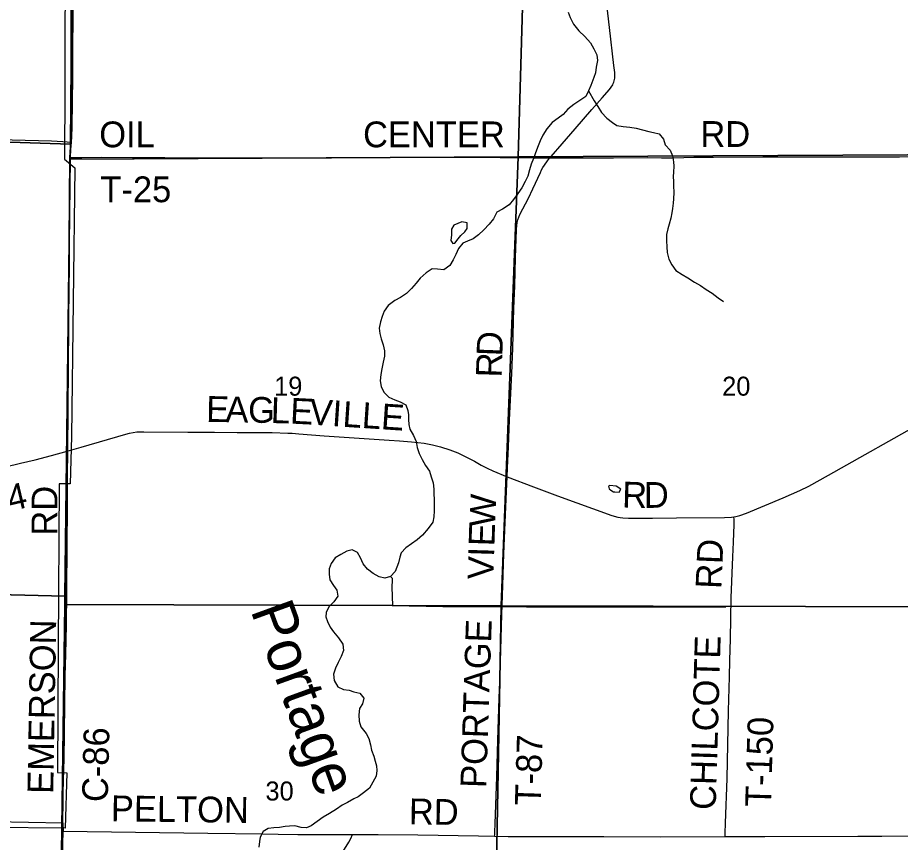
# Model space of a CAD drawing. Extents: x 1443599 to 1910620, y 1028088 to 1361369.
# Drawn here: x 1682963 to 1693235, y 1162784 to 1172379 of the extents above; entities that cross this region are included whole.
import ezdxf

# ---------------------------------------------------------------- set-up
doc = ezdxf.new("R2010")
doc.units = 0
for name, color, linetype in [('GM_X_County_Road', 7, 'Continuous'), ('GM_X_County_Road_Text', 7, 'Continuous'), ('GM_X_Major_River', 7, 'Continuous'), ('GM_X_Major_River_Text', 7, 'Continuous'), ('GM_X_Minor_Lake', 7, 'Continuous'), ('GM_X_Minor_River', 7, 'Continuous'), ('GM_X_Section', 7, 'Continuous'), ('GM_X_Section_Text', 7, 'Continuous'), ('GM_X_Township', 7, 'Continuous'), ('GM_X_Township_Road', 7, 'Continuous'), ('GM_X_Township_Road_Text', 7, 'Continuous')]:
    doc.layers.add(name, color=color, linetype=linetype)

msp = doc.modelspace()

# ---------------------------------------------------------------- linework, layer by layer
at = {"layer": 'GM_X_County_Road'}
for points in [[(1683590, 1170929), (1683595, 1170994), (1683598, 1171109), (1683605, 1171686), (1683607, 1172060), (1683609, 1172350), (1683612, 1172924), (1683614, 1173254), (1683611, 1173384)], [(1683579, 1170752), (1683583, 1170847), (1683590, 1170929)], [(1683539, 1167334), (1683542, 1167414), (1683546, 1167591), (1683550, 1167869), (1683552, 1168070), (1683556, 1168581), (1683559, 1168893), (1683563, 1169270), (1683565, 1169433), (1683567, 1169742), (1683570, 1170087), (1683572, 1170399), (1683575, 1170650), (1683579, 1170752)], [(1683490, 1163011), (1683489, 1163099), (1683491, 1163314), (1683495, 1163492), (1683502, 1163642), (1683506, 1163744), (1683509, 1164063), (1683513, 1164388), (1683518, 1164721), (1683523, 1164974), (1683531, 1165312), (1683537, 1165698), (1683539, 1166255), (1683542, 1166665), (1683543, 1166892), (1683538, 1167107), (1683537, 1167264), (1683539, 1167334)], [(1678210, 1163117), (1678747, 1163103), (1679108, 1163091), (1680009, 1163079), (1680419, 1163071), (1681435, 1163051), (1682288, 1163036), (1683490, 1163011)], [(1683490, 1163011), (1683492, 1162913)], [(1683492, 1162913), (1685175, 1162891), (1685815, 1162884), (1685995, 1162880), (1686225, 1162875), (1686619, 1162877), (1686861, 1162877)], [(1686861, 1162877), (1687160, 1162876), (1687620, 1162872), (1688326, 1162859), (1688514, 1162855)], [(1688514, 1162855), (1688670, 1162851), (1689786, 1162851), (1690443, 1162850), (1691195, 1162851)], [(1691195, 1162851), (1691657, 1162851), (1692741, 1162856), (1693020, 1162857), (1693834, 1162862)]]:
    msp.add_lwpolyline(points, dxfattribs=at)
at = {"layer": 'GM_X_Major_River'}
for points in [[(1689368, 1172444), (1689394, 1172379), (1689433, 1172305), (1689495, 1172225), (1689563, 1172158), (1689630, 1172086), (1689670, 1172018), (1689704, 1171947), (1689712, 1171879), (1689697, 1171805), (1689687, 1171737), (1689669, 1171682)], [(1689669, 1171682), (1689634, 1171591), (1689606, 1171529), (1689574, 1171462), (1689506, 1171416), (1689435, 1171367), (1689367, 1171315), (1689311, 1171253), (1689253, 1171211), (1689182, 1171159), (1689123, 1171085), (1689075, 1171012), (1689043, 1170945), (1689014, 1170870), (1688984, 1170795), (1688966, 1170741), (1688940, 1170674), (1688921, 1170608), (1688901, 1170535), (1688869, 1170472), (1688829, 1170399), (1688784, 1170334), (1688732, 1170264), (1688682, 1170203), (1688606, 1170152), (1688541, 1170116), (1688501, 1170039), (1688450, 1169975), (1688390, 1169909), (1688328, 1169851), (1688265, 1169805), (1688198, 1169777), (1688145, 1169757), (1688093, 1169694), (1688063, 1169623), (1688033, 1169562), (1687992, 1169495), (1687921, 1169447), (1687851, 1169454), (1687787, 1169456), (1687718, 1169412), (1687649, 1169350), (1687599, 1169290), (1687547, 1169228), (1687488, 1169171), (1687418, 1169122), (1687351, 1169088), (1687275, 1169032), (1687227, 1168966), (1687207, 1168902), (1687184, 1168839), (1687172, 1168767), (1687178, 1168703), (1687192, 1168642), (1687216, 1168573), (1687234, 1168504), (1687231, 1168440), (1687217, 1168369), (1687201, 1168295), (1687188, 1168229), (1687182, 1168155), (1687194, 1168089), (1687224, 1168020), (1687284, 1167964), (1687351, 1167933), (1687414, 1167909), (1687479, 1167875), (1687503, 1167808), (1687511, 1167757), (1687513, 1167703), (1687516, 1167647), (1687526, 1167591), (1687569, 1167519), (1687599, 1167448), (1687611, 1167379), (1687637, 1167308), (1687670, 1167239), (1687708, 1167168), (1687758, 1167102), (1687774, 1167037), (1687799, 1166968), (1687805, 1166892), (1687807, 1166839), (1687809, 1166773), (1687811, 1166713), (1687811, 1166641), (1687807, 1166573), (1687796, 1166511), (1687742, 1166437), (1687673, 1166359), (1687612, 1166303), (1687546, 1166259), (1687482, 1166211), (1687425, 1166153), (1687409, 1166101), (1687395, 1166038), (1687355, 1165935), (1687301, 1165877), (1687235, 1165859), (1687169, 1165873), (1687102, 1165911)], [(1687102, 1165911), (1687034, 1165962), (1686984, 1166026), (1686952, 1166093), (1686920, 1166156), (1686855, 1166186), (1686793, 1166172), (1686725, 1166134), (1686658, 1166095), (1686612, 1166030), (1686590, 1165965), (1686588, 1165903), (1686598, 1165838), (1686640, 1165773), (1686678, 1165717), (1686688, 1165649), (1686643, 1165584), (1686585, 1165524), (1686553, 1165459), (1686551, 1165407), (1686568, 1165354), (1686602, 1165287), (1686640, 1165235), (1686698, 1165163), (1686747, 1165088), (1686755, 1165017), (1686730, 1164946), (1686692, 1164877), (1686662, 1164810), (1686638, 1164741), (1686645, 1164668), (1686689, 1164593), (1686754, 1164564), (1686822, 1164554), (1686875, 1164536), (1686945, 1164518), (1686991, 1164460), (1686975, 1164396), (1686941, 1164342), (1686934, 1164266), (1686936, 1164195), (1686958, 1164129), (1687019, 1164050), (1687049, 1163991), (1687069, 1163920), (1687081, 1163858), (1687107, 1163785), (1687125, 1163728), (1687139, 1163673), (1687145, 1163619), (1687135, 1163555), (1687097, 1163483), (1687056, 1163416), (1686987, 1163362), (1686925, 1163314), (1686874, 1163292), (1686801, 1163248), (1686740, 1163216), (1686674, 1163170), (1686594, 1163121), (1686517, 1163077), (1686378, 1162978), (1686325, 1162951), (1686261, 1162958), (1686189, 1162976), (1686125, 1162974), (1686075, 1162968), (1686009, 1162958), (1685946, 1162952), (1685878, 1162947), (1685819, 1162910), (1685787, 1162843), (1685779, 1162792), (1685771, 1162726)]]:
    msp.add_lwpolyline(points, dxfattribs=at)
at = {"layer": 'GM_X_Minor_Lake'}
for p, q in [((1688013, 1169918), (1688014, 1169852)), ((1689898, 1166861), (1689914, 1166863))]:
    msp.add_line(p, q, dxfattribs=at)
for points in [[(1688014, 1169852), (1688006, 1169786), (1688028, 1169753), (1688052, 1169754), (1688089, 1169804), (1688122, 1169843), (1688167, 1169886), (1688194, 1169925), (1688193, 1169990), (1688133, 1170005), (1688040, 1169963), (1688013, 1169918)], [(1689914, 1166863), (1689962, 1166858), (1689981, 1166895), (1689928, 1166927), (1689856, 1166934), (1689838, 1166927), (1689845, 1166897), (1689865, 1166880), (1689898, 1166861)]]:
    msp.add_lwpolyline(points, dxfattribs=at)
at = {"layer": 'GM_X_Minor_River'}
for points in [[(1683506, 1181922), (1683576, 1181602), (1683614, 1181365), (1683590, 1180632), (1683563, 1178664), (1683702, 1178541), (1683687, 1176701), (1683662, 1174382), (1683655, 1173511), (1683516, 1173367), (1683513, 1171543), (1683508, 1170733), (1683629, 1170633), (1683610, 1169074), (1683591, 1167507), (1683576, 1166954), (1683448, 1166955), (1683434, 1165063), (1683426, 1163597), (1683534, 1163591), (1683515, 1162948), (1682657, 1162955), (1680246, 1162983)], [(1689606, 1171529), (1689672, 1171413), (1689716, 1171345), (1689758, 1171276), (1689818, 1171210), (1689884, 1171159), (1689937, 1171125), (1690009, 1171113), (1690088, 1171104), (1690160, 1171092), (1690235, 1171073), (1690307, 1171055), (1690363, 1171043), (1690428, 1171027), (1690480, 1170965), (1690498, 1170898), (1690558, 1170838), (1690582, 1170771), (1690595, 1170700), (1690598, 1170650), (1690596, 1170582), (1690592, 1170530), (1690594, 1170474), (1690596, 1170421), (1690598, 1170343), (1690596, 1170273), (1690590, 1170219), (1690584, 1170159), (1690576, 1170107), (1690566, 1170048), (1690546, 1169978), (1690528, 1169921), (1690516, 1169857), (1690513, 1169781), (1690517, 1169712), (1690521, 1169648), (1690543, 1169571), (1690578, 1169502), (1690624, 1169436), (1690695, 1169392), (1690761, 1169351), (1690840, 1169301), (1690909, 1169262), (1690977, 1169218), (1691046, 1169175), (1691116, 1169121), (1691179, 1169077)], [(1687301, 1165877), (1687323, 1165856), (1687322, 1165836), (1687317, 1165752), (1687324, 1165539), (1687910, 1165529), (1688885, 1165526), (1690184, 1165525), (1691206, 1165526)]]:
    msp.add_lwpolyline(points, dxfattribs=at)
at = {"layer": 'GM_X_Section'}
for points in [[(1678394, 1176372), (1683624, 1176213), (1683621, 1175989), (1683578, 1170908), (1678288, 1171080)], [(1688941, 1175979), (1694213, 1176083), (1694075, 1170786), (1688786, 1170761)], [(1683621, 1175989), (1688941, 1175979), (1688786, 1170761), (1683576, 1170734), (1683578, 1170908)], [(1683578, 1170908), (1683576, 1170734), (1683514, 1165647), (1678214, 1165781), (1678288, 1171080)], [(1688786, 1170761), (1688589, 1165537), (1683513, 1165551), (1683514, 1165647), (1683576, 1170734)], [(1688786, 1170761), (1694075, 1170786), (1693900, 1165524), (1688589, 1165537)], [(1678214, 1165781), (1683514, 1165647), (1683513, 1165551), (1683444, 1160353), (1678169, 1160435)], [(1683513, 1165551), (1688589, 1165537), (1688492, 1160184), (1683441, 1160257), (1683444, 1160353)], [(1688589, 1165537), (1693900, 1165524), (1693769, 1160176), (1688492, 1160184)]]:
    msp.add_lwpolyline(points, close=True, dxfattribs=at)
at = {"layer": 'GM_X_Township'}
for points in [[(1681032, 1186821), (1683679, 1186812), (1683685, 1182383), (1683692, 1181349), (1683667, 1180336), (1683654, 1178870), (1683653, 1178676), (1683622, 1176760), (1683591, 1173346), (1683582, 1170936), (1683569, 1170753), (1683542, 1167341), (1683487, 1162999), (1683485, 1162903), (1683433, 1160340), (1683431, 1160224), (1683394, 1157657), (1683283, 1155017), (1683083, 1155019), (1681204, 1155095)], [(1693997, 1154808), (1693049, 1154849), (1692309, 1154864), (1692192, 1154867), (1690915, 1154906), (1689703, 1154870), (1687820, 1154935), (1687303, 1154948), (1686367, 1154971), (1684123, 1155008), (1683283, 1155017), (1683394, 1157657), (1683431, 1160224), (1683433, 1160340), (1683485, 1162903), (1683487, 1162999), (1683542, 1167341), (1683569, 1170753), (1683582, 1170936), (1683591, 1173346)]]:
    msp.add_lwpolyline(points, dxfattribs=at)
at = {"layer": 'GM_X_Township_Road'}
for points in [[(1689154, 1170747), (1689172, 1170765), (1689301, 1170913), (1689452, 1171087), (1689645, 1171311), (1689765, 1171446), (1689851, 1171545), (1689871, 1171571), (1689888, 1171599), (1689895, 1171614), (1689901, 1171629), (1689906, 1171645), (1689910, 1171661), (1689912, 1171677), (1689913, 1171693), (1689913, 1171710), (1689912, 1171742), (1689903, 1171824), (1689851, 1172264), (1689793, 1172770), (1689759, 1173063), (1689719, 1173401)], [(1678296, 1171095), (1678387, 1171090), (1679683, 1171050), (1680060, 1171039), (1680815, 1171014), (1681028, 1171009), (1682456, 1170971), (1682899, 1170958), (1683358, 1170945), (1683489, 1170939), (1683538, 1170934), (1683590, 1170929)], [(1683579, 1170752), (1683611, 1170752), (1683710, 1170753), (1683939, 1170754), (1684300, 1170751), (1684678, 1170751), (1684924, 1170750), (1685219, 1170749), (1685597, 1170748), (1685942, 1170747), (1686614, 1170750), (1687008, 1170751), (1687419, 1170754), (1687794, 1170755), (1688075, 1170755), (1688272, 1170755), (1688578, 1170751), (1688774, 1170751), (1688977, 1170749), (1689109, 1170747), (1689154, 1170747)], [(1688659, 1167037), (1688664, 1167141), (1688676, 1167387), (1688689, 1167698), (1688714, 1168239), (1688724, 1168535), (1688739, 1168994), (1688748, 1169257), (1688757, 1169585), (1688769, 1169913), (1688773, 1169962), (1688778, 1169995), (1688785, 1170027), (1688795, 1170058), (1688809, 1170088), (1688907, 1170278), (1688960, 1170387), (1689046, 1170577), (1689060, 1170609), (1689075, 1170634), (1689120, 1170703), (1689149, 1170742), (1689154, 1170747)], [(1689154, 1170747), (1689437, 1170748), (1689896, 1170750), (1690290, 1170751), (1690454, 1170749), (1690599, 1170750), (1690831, 1170755), (1691061, 1170757), (1691635, 1170758), (1691898, 1170759), (1692341, 1170760), (1692521, 1170761), (1692686, 1170759), (1693030, 1170759), (1693227, 1170761), (1693440, 1170762)], [(1691296, 1166570), (1691299, 1166570), (1691320, 1166575), (1691368, 1166587), (1691446, 1166615), (1691870, 1166791), (1692066, 1166877), (1692169, 1166928), (1692399, 1167055), (1693529, 1167691), (1693929, 1167913), (1693985, 1167943)], [(1683539, 1167334), (1683704, 1167380), (1684224, 1167534), (1684264, 1167545), (1684307, 1167554), (1684351, 1167559), (1684433, 1167562), (1684942, 1167557), (1685253, 1167555), (1685516, 1167553), (1685926, 1167551), (1686106, 1167545), (1686156, 1167543), (1686234, 1167537)], [(1686234, 1167537), (1686532, 1167515), (1687285, 1167464), (1687408, 1167455), (1687547, 1167445), (1687693, 1167428), (1687790, 1167410), (1687885, 1167386), (1687994, 1167351), (1688085, 1167315), (1688188, 1167265), (1688280, 1167218), (1688357, 1167173), (1688427, 1167136), (1688494, 1167106), (1688659, 1167037)], [(1678240, 1166491), (1678287, 1166494), (1678368, 1166499), (1679285, 1166554), (1680072, 1166596), (1680448, 1166614), (1680629, 1166625), (1680678, 1166630), (1680729, 1166637), (1680807, 1166655), (1681125, 1166737), (1681888, 1166934), (1682349, 1167043), (1682642, 1167111), (1682822, 1167153), (1682995, 1167194), (1683166, 1167233), (1683357, 1167283), (1683539, 1167334)], [(1688514, 1162855), (1688515, 1162872), (1688517, 1162907), (1688521, 1163001), (1688538, 1163548), (1688552, 1163974), (1688568, 1164460), (1688578, 1164750), (1688599, 1165435), (1688607, 1165655), (1688623, 1166140), (1688644, 1166686), (1688655, 1166957), (1688659, 1167037)], [(1688659, 1167037), (1688661, 1167036), (1688967, 1166919), (1689245, 1166817), (1689877, 1166587), (1689946, 1166568), (1689973, 1166563), (1690006, 1166560), (1690072, 1166556), (1690351, 1166556), (1690631, 1166559), (1691189, 1166563), (1691271, 1166567), (1691296, 1166570)], [(1691195, 1162851), (1691196, 1162864), (1691196, 1162890), (1691201, 1163009), (1691219, 1163525), (1691237, 1164314), (1691248, 1164708), (1691253, 1164901), (1691259, 1165152), (1691266, 1165628), (1691286, 1166105), (1691293, 1166276), (1691302, 1166483), (1691303, 1166525), (1691302, 1166540), (1691301, 1166548), (1691298, 1166563), (1691296, 1166570)], [(1683450, 1160360), (1683453, 1160464), (1683466, 1161298), (1683471, 1161644), (1683474, 1161820), (1683477, 1162056), (1683482, 1162271), (1683487, 1162603), (1683489, 1162758), (1683492, 1162913)], [(1685273, 1160233), (1685534, 1160665), (1685670, 1160893), (1685773, 1161067), (1685855, 1161208), (1685936, 1161344), (1686019, 1161485), (1686103, 1161625), (1686208, 1161794), (1686304, 1161951), (1686604, 1162439), (1686816, 1162786), (1686846, 1162836), (1686850, 1162847), (1686854, 1162856), (1686861, 1162877)]]:
    msp.add_lwpolyline(points, dxfattribs=at)

# ---------------------------------------------------------------- texts
at = {"layer": 'GM_X_County_Road_Text'}
for s, rotation, p in [('RD', 90, (1683426, 1166353)), ('EMERSON', 89.0023, (1683377, 1163346)), ('C-86', 88.6829, (1684012, 1163250)), ('PELTON', 359.2816, (1684047, 1163030)), ('RD', 359.0168, (1687514, 1162995))]:
    msp.add_text(s, height=300, rotation=rotation, dxfattribs=at).set_placement(p)
at = {"layer": 'GM_X_Major_River_Text'}
msp.add_text('Portage', height=500.1, rotation=289.9545, dxfattribs=at).set_placement((1685670, 1165485))
at = {"layer": 'GM_X_Section_Text'}
for s, p in [('19', (1685948, 1167981)), ('20', (1691162, 1167981)), ('30', (1685847, 1163271))]:
    msp.add_text(s, height=221, rotation=0, dxfattribs=at).set_placement(p)
at = {"layer": 'GM_X_Township_Road_Text'}
for s, rotation, p in [('OIL', 0, (1683913, 1170871)), ('CENTER', 0, (1686983, 1170871)), ('RD', 0, (1690909, 1170875)), ('T-25', 0, (1683926, 1170232)), ('D', 87.8649, (1688603, 1168436)), ('R', 88.3059, (1688596, 1168190)), ('E', 358.9971, (1685155, 1167677)), ('A', 358.9945, (1685379, 1167673)), ('G', 358.98, (1685643, 1167668)), ('L', 358.3841, (1685906, 1167663)), ('E', 357.1404, (1686129, 1167657)), ('V', 356.2308, (1686352, 1167646)), ('I', 356.1724, (1686615, 1167629)), ('L', 356.1727, (1686738, 1167620)), ('L', 356.1745, (1686962, 1167606)), ('E', 356.2566, (1687186, 1167591)), ('T-34', 13.1839, (1682291, 1166497)), ('R', 358.505, (1689995, 1166681)), ('D', 0.5112, (1690252, 1166675)), ('W', 87.3624, (1688518, 1166449)), ('E', 88.2083, (1688511, 1166226)), ('RD', 87.5332, (1691152, 1165729)), ('V', 88.2184, (1688499, 1165839)), ('I', 88.2192, (1688507, 1166103)), ('PORTAGE', 88.061, (1688415, 1163413)), ('CHILCOTE', 88.3315, (1691086, 1163158)), ('T-150', 88.3162, (1691729, 1163192)), ('T-87', 88.2318, (1689049, 1163209))]:
    msp.add_text(s, height=300, rotation=rotation, dxfattribs=at).set_placement(p)

doc.saveas('drawing.dxf')
